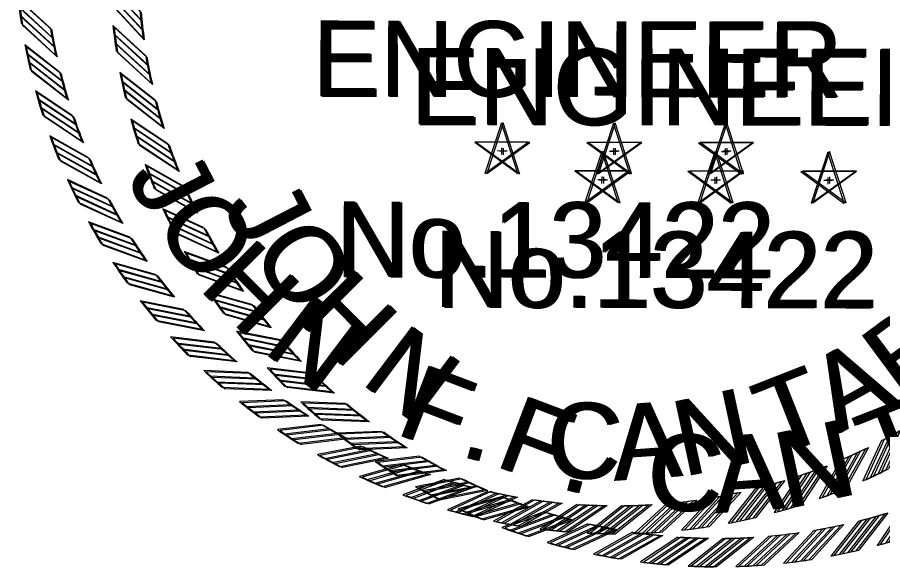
# Model space of a CAD drawing. Extents: x 1373884 to 1377798, y 1168424 to 1170626.
# Drawn here: x 1376716 to 1376888.6, y 1168432.1 to 1168541.9 of the extents above; entities that cross this region are included whole.
import ezdxf

# ---------------------------------------------------------------- set-up
doc = ezdxf.new("R2010")
doc.units = 0
for name, color, linetype in [('Default', 7, 'Continuous'), ('G-ANNO-SYMB', 7, 'Continuous'), ('G-ANNO-TEXT', 7, 'Continuous')]:
    doc.layers.add(name, color=color, linetype=linetype)

# ---------------------------------------------------------------- blocks, each defined once
blk = doc.blocks.new('STAR')
at = {"layer": 'Default'}
for p, q in [((-0.0001, 0.0615), (-0.0366, -0.0504)), ((0.0362, -0.0503), (0, 0.0617)), ((0.0587, 0.0188), (-0.059, 0.0189)), ((-0.0589, 0.0188), (0.0363, -0.0505)), ((-0.0365, -0.0503), (0.0589, 0.0188)), ((-0.0085, 0), (0.009, 0)), ((0, 0.0063), (0, -0.0085))]:
    blk.add_line(p, q, dxfattribs=at)
blk = doc.blocks.new('RP')
at = {"layer": 'Default'}
for p, q in [((-0.0781, 1.2656), (0.003, 1.33)), ((-0.058, 1.2667), (0.0216, 1.3299)), ((-0.0375, 1.2674), (0.0405, 1.3294)), ((-0.0176, 1.2679), (0.059, 1.3287))]:
    blk.add_line(p, q, dxfattribs=at)
for radius, start, end in [(1.33, 87.4562, 89.8699), (1.268, 90.7933, 93.5307)]:
    blk.add_arc((0, 0), radius, start, end, dxfattribs=at)

msp = doc.modelspace()

# ---------------------------------------------------------------- block references
at = {"layer": 'Default'}
for name, p, xscale, yscale, rotation in [('RP', (1376855.59, 1168553.5), 91.1765534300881, 91.17655343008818, 94.30419999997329), ('RP', (1376855.79, 1168553.54), 91.1765534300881, 91.17655343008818, 94.5000001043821), ('RP', (1376855.59, 1168553.5), 91.17655343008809, 91.17655343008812, 98.8041999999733), ('RP', (1376855.79, 1168553.54), 91.17655343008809, 91.17655343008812, 99.0000001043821), ('RP', (1376855.59, 1168553.5), 91.1765534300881, 91.17655343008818, 103.30419999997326), ('RP', (1376855.79, 1168553.54), 91.17655343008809, 91.17655343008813, 103.50000010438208), ('RP', (1376855.59, 1168553.5), 91.1765534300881, 91.1765534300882, 107.80419999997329), ('RP', (1376855.79, 1168553.54), 91.17655343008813, 91.17655343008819, 108.0000001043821), ('RP', (1376855.59, 1168553.5), 91.1765534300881, 91.17655343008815, 112.30419999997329), ('STAR', (1376832.54, 1168509.52), 91.17655343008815, 91.1765534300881, -0.1958000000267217), ('STAR', (1376832.9, 1168509.47), 91.17655343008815, 91.1765534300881, 1.0438208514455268e-07), ('STAR', (1376855.1, 1168509.44), 91.17655343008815, 91.1765534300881, -0.1958000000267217), ('STAR', (1376855.45, 1168509.47), 91.17655343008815, 91.1765534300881, 1.0438208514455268e-07), ('STAR', (1376877.65, 1168509.37), 91.17655343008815, 91.1765534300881, -0.1958000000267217), ('STAR', (1376878.01, 1168509.47), 91.17655343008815, 91.1765534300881, 1.0438208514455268e-07), ('RP', (1376855.79, 1168553.54), 91.1765534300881, 91.17655343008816, 112.5000001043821), ('RP', (1376855.59, 1168553.5), 91.17655343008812, 91.17655343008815, 116.80419999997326), ('RP', (1376855.79, 1168553.54), 91.17655343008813, 91.17655343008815, 117.0000001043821), ('RP', (1376855.59, 1168553.5), 91.17655343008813, 91.17655343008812, 121.30419999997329), ('RP', (1376855.79, 1168553.54), 91.17655343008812, 91.17655343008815, 121.5000001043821), ('RP', (1376855.59, 1168553.5), 91.17655343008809, 91.17655343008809, 125.80419999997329), ('RP', (1376855.79, 1168553.54), 91.17655343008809, 91.17655343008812, 126.00000010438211), ('RP', (1376855.59, 1168553.5), 91.1765534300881, 91.17655343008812, 130.3041999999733), ('RP', (1376855.79, 1168553.54), 91.17655343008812, 91.1765534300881, 130.50000010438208), ('RP', (1376855.59, 1168553.5), 91.17655343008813, 91.17655343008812, 134.8041999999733), ('RP', (1376855.79, 1168553.54), 91.17655343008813, 91.17655343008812, 135.00000010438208), ('RP', (1376855.59, 1168553.5), 91.17655343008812, 91.17655343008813, 139.30419999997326), ('RP', (1376855.79, 1168553.54), 91.17655343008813, 91.17655343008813, 139.50000010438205), ('RP', (1376855.59, 1168553.5), 91.17655343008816, 91.17655343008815, 143.8041999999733), ('RP', (1376855.79, 1168553.54), 91.17655343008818, 91.17655343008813, 144.00000010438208), ('RP', (1376855.59, 1168553.5), 91.17655343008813, 91.17655343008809, 148.3041999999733), ('RP', (1376855.79, 1168553.54), 91.17655343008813, 91.17655343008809, 148.50000010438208), ('RP', (1376855.59, 1168553.5), 91.17655343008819, 91.17655343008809, 152.8041999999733), ('RP', (1376855.79, 1168553.54), 91.17655343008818, 91.17655343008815, 153.00000010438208), ('RP', (1376855.59, 1168553.5), 91.17655343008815, 91.1765534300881, 157.3041999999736), ('RP', (1376855.79, 1168553.54), 91.17655343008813, 91.17655343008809, 157.50000010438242), ('RP', (1376855.59, 1168553.5), 91.17655343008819, 91.17655343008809, 161.8041999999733), ('RP', (1376855.79, 1168553.54), 91.17655343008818, 91.17655343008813, 162.00000010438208), ('RP', (1376855.59, 1168553.5), 91.17655343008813, 91.17655343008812, -162.19580000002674), ('RP', (1376855.79, 1168553.54), 91.17655343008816, 91.1765534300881, -161.99999989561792), ('RP', (1376855.59, 1168553.5), 91.17655343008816, 91.17655343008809, 166.3041999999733), ('RP', (1376855.79, 1168553.54), 91.17655343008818, 91.17655343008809, 166.50000010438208), ('RP', (1376855.59, 1168553.5), 91.17655343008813, 91.17655343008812, -166.69580000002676), ('RP', (1376855.79, 1168553.54), 91.17655343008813, 91.17655343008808, -166.49999989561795), ('RP', (1376855.59, 1168553.5), 91.17655343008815, 91.1765534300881, 170.8041999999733), ('RP', (1376855.79, 1168553.54), 91.17655343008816, 91.17655343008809, 171.00000010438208), ('RP', (1376855.59, 1168553.5), 91.1765534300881, 91.17655343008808, -171.19580000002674), ('RP', (1376855.79, 1168553.54), 91.17655343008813, 91.17655343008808, -170.99999989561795), ('RP', (1376855.59, 1168553.5), 91.17655343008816, 91.1765534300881, 175.3041999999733), ('RP', (1376855.79, 1168553.54), 91.17655343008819, 91.17655343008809, 175.50000010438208), ('RP', (1376855.59, 1168553.5), 91.17655343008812, 91.1765534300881, -175.69580000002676), ('RP', (1376855.79, 1168553.54), 91.17655343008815, 91.17655343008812, -175.49999989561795), ('RP', (1376855.59, 1168553.5), 91.17655343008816, 91.17655343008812, 179.8041999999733), ('RP', (1376855.79, 1168553.54), 91.17655343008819, 91.17655343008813, -179.99999989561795)]:
    msp.add_blockref(name, p, dxfattribs=dict(at, xscale=xscale, yscale=yscale, rotation=rotation))
at = {"layer": 'G-ANNO-SYMB'}
for name, p, xscale, yscale, rotation in [('RP', (1376835.36, 1168558.79), 90.20715837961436, 90.20715837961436, 98.8041999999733), ('RP', (1376835.56, 1168558.82), 90.20715837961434, 90.20715837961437, 99.0000001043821), ('RP', (1376835.36, 1168558.79), 90.20715837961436, 90.2071583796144, 103.30419999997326), ('RP', (1376835.56, 1168558.82), 90.20715837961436, 90.2071583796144, 103.50000010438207), ('RP', (1376835.36, 1168558.79), 90.20715837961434, 90.20715837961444, 107.80419999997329), ('RP', (1376835.56, 1168558.82), 90.20715837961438, 90.20715837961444, 108.0000001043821), ('RP', (1376835.36, 1168558.79), 90.20715837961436, 90.20715837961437, 112.30419999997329), ('RP', (1376835.56, 1168558.82), 90.20715837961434, 90.2071583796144, 112.5000001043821), ('STAR', (1376812.56, 1168515.27), 90.2071583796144, 90.20715837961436, -0.19580000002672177), ('STAR', (1376812.91, 1168515.23), 90.2071583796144, 90.20715837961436, 1.0438208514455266e-07), ('STAR', (1376834.88, 1168515.19), 90.2071583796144, 90.20715837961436, -0.19580000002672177), ('STAR', (1376835.23, 1168515.23), 90.2071583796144, 90.20715837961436, 1.0438208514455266e-07), ('STAR', (1376857.19, 1168515.12), 90.2071583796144, 90.20715837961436, -0.19580000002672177), ('STAR', (1376857.54, 1168515.23), 90.2071583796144, 90.20715837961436, 1.0438208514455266e-07), ('RP', (1376835.36, 1168558.79), 90.20715837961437, 90.2071583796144, 116.80419999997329), ('RP', (1376835.56, 1168558.82), 90.20715837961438, 90.2071583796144, 117.0000001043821), ('RP', (1376835.36, 1168558.79), 90.20715837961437, 90.20715837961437, 121.30419999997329), ('RP', (1376835.56, 1168558.82), 90.20715837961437, 90.20715837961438, 121.5000001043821), ('RP', (1376835.36, 1168558.79), 90.20715837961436, 90.20715837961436, 125.80419999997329), ('RP', (1376835.56, 1168558.82), 90.20715837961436, 90.20715837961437, 126.00000010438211), ('RP', (1376835.36, 1168558.79), 90.20715837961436, 90.20715837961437, 130.3041999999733), ('RP', (1376835.56, 1168558.82), 90.20715837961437, 90.20715837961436, 130.50000010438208), ('RP', (1376835.36, 1168558.79), 90.20715837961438, 90.20715837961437, 134.80419999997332), ('RP', (1376835.56, 1168558.82), 90.2071583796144, 90.20715837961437, 135.00000010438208), ('RP', (1376835.36, 1168558.79), 90.20715837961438, 90.20715837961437, 139.30419999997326), ('RP', (1376835.56, 1168558.82), 90.20715837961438, 90.20715837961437, 139.50000010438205), ('RP', (1376835.36, 1168558.79), 90.20715837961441, 90.20715837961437, 143.8041999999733), ('RP', (1376835.56, 1168558.82), 90.20715837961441, 90.20715837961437, 144.00000010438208), ('RP', (1376835.36, 1168558.79), 90.20715837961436, 90.20715837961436, 148.3041999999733), ('RP', (1376835.56, 1168558.82), 90.20715837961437, 90.20715837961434, 148.50000010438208), ('RP', (1376835.36, 1168558.79), 90.20715837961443, 90.20715837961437, 152.8041999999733), ('RP', (1376835.56, 1168558.82), 90.20715837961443, 90.2071583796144, 153.00000010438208), ('RP', (1376835.36, 1168558.79), 90.20715837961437, 90.20715837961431, -153.1958000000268), ('RP', (1376835.56, 1168558.82), 90.20715837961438, 90.20715837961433, -152.99999989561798), ('RP', (1376835.36, 1168558.79), 90.2071583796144, 90.20715837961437, -157.6958000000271), ('RP', (1376835.56, 1168558.82), 90.20715837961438, 90.20715837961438, -157.4999998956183), ('RP', (1376835.36, 1168558.79), 90.2071583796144, 90.20715837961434, 157.3041999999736), ('RP', (1376835.56, 1168558.82), 90.20715837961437, 90.20715837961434, 157.50000010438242), ('RP', (1376835.56, 1168558.82), 90.20715837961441, 90.20715837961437, -161.99999989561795), ('RP', (1376835.36, 1168558.79), 90.20715837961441, 90.20715837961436, 161.8041999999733), ('RP', (1376835.56, 1168558.82), 90.20715837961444, 90.20715837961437, 162.00000010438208), ('RP', (1376835.36, 1168558.79), 90.2071583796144, 90.20715837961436, -162.19580000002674), ('RP', (1376835.36, 1168558.79), 90.20715837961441, 90.20715837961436, 166.3041999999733), ('RP', (1376835.56, 1168558.82), 90.20715837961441, 90.20715837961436, 166.50000010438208), ('RP', (1376835.36, 1168558.79), 90.2071583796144, 90.20715837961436, -166.69580000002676), ('RP', (1376835.56, 1168558.82), 90.20715837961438, 90.20715837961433, -166.49999989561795), ('RP', (1376835.56, 1168558.82), 90.20715837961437, 90.20715837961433, -170.99999989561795), ('RP', (1376835.36, 1168558.79), 90.2071583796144, 90.20715837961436, 170.8041999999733), ('RP', (1376835.56, 1168558.82), 90.2071583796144, 90.20715837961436, 171.00000010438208), ('RP', (1376835.36, 1168558.79), 90.20715837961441, 90.20715837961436, 175.3041999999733), ('RP', (1376835.56, 1168558.82), 90.20715837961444, 90.20715837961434, 175.50000010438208), ('RP', (1376835.36, 1168558.79), 90.20715837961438, 90.20715837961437, -175.69580000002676), ('RP', (1376835.56, 1168558.82), 90.2071583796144, 90.20715837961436, -175.49999989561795), ('RP', (1376835.36, 1168558.79), 90.20715837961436, 90.20715837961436, -171.19580000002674), ('RP', (1376835.36, 1168558.79), 90.2071583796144, 90.20715837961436, 179.8041999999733), ('RP', (1376835.56, 1168558.82), 90.20715837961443, 90.20715837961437, -179.99999989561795)]:
    msp.add_blockref(name, p, dxfattribs=dict(at, xscale=xscale, yscale=yscale, rotation=rotation))

# ---------------------------------------------------------------- texts
at = {"layer": 'Default'}
for s, height, rotation, p in [('ENGINEER', 15.285, 359.8042, (1376794.33, 1168520.51)), ('ENGINEER', 15.285, 0, (1376794.65, 1168520.33)), ('J', 15.28, 297.2813, (1376756.79, 1168504.38)), ('J', 15.28, 297.4771, (1376757.16, 1168504.07)), ('O', 15.28, 304.1899, (1376762.2, 1168495)), ('O', 15.28, 304.3857, (1376762.61, 1168494.72)), ('No.13422', 15.225, 359.8042, (1376799.03, 1168484.06)), ('No.13422', 15.225, 0, (1376799.48, 1168483.9)), ('H', 15.28, 314.7447, (1376771.22, 1168481.84)), ('H', 15.28, 314.9405, (1376771.67, 1168481.58)), ('N', 15.28, 322.9417, (1376784.12, 1168469.06)), ('N', 15.28, 323.1375, (1376784.62, 1168468.85)), ('F', 15.28, 339.0288, (1376810.8, 1168452.5)), ('F', 15.28, 339.2246, (1376811.35, 1168452.38)), ('T', 15.28, 21.4329, (1376887.56, 1168447.5)), ('T', 15.28, 21.6287, (1376888.13, 1168447.65)), ('N', 15.28, 12.0703, (1376869.12, 1168443.69)), ('N', 15.28, 12.2661, (1376869.7, 1168443.77)), ('C', 15.28, 356.1028, (1376841.13, 1168443.92)), ('C', 15.28, 356.2986, (1376841.71, 1168443.91)), ('A', 15.28, 3.9092, (1376855.15, 1168442.91)), ('A', 15.28, 4.105, (1376855.73, 1168442.94)), ('.', 15.28, 344.7037, (1376823.84, 1168447.98)), ('.', 15.28, 344.8995, (1376824.41, 1168447.91))]:
    msp.add_text(s, height=height, rotation=rotation, dxfattribs=at).set_placement(p)
at = {"layer": 'G-ANNO-TEXT'}
for s, height, rotation, p in [('ENGINEER', 15.122, 359.8042, (1376774.76, 1168526.14)), ('ENGINEER', 15.122, 0, (1376775.07, 1168525.97)), ('J', 15.12, 297.2813, (1376737.61, 1168510.18)), ('J', 15.12, 297.4771, (1376737.98, 1168509.88)), ('O', 15.12, 304.1899, (1376742.97, 1168500.91)), ('O', 15.12, 304.3857, (1376743.37, 1168500.63)), ('No.13422', 15.063, 359.8042, (1376779.41, 1168490.08)), ('No.13422', 15.063, 0, (1376779.85, 1168489.92)), ('H', 15.12, 314.7447, (1376751.89, 1168487.88)), ('H', 15.12, 314.9405, (1376752.33, 1168487.63)), ('N', 15.12, 322.9417, (1376764.66, 1168475.24)), ('N', 15.12, 323.1375, (1376765.14, 1168475.03)), ('B', 15.12, 36.505, (1376892.12, 1168465.24)), ('B', 15.12, 36.7008, (1376892.65, 1168465.47)), ('A', 15.12, 28.8562, (1376879.56, 1168458.65)), ('A', 15.12, 29.052, (1376880.11, 1168458.83)), ('F', 15.12, 339.0288, (1376791.05, 1168458.86)), ('F', 15.12, 339.2246, (1376791.6, 1168458.74)), ('T', 15.12, 21.4329, (1376866.99, 1168453.91)), ('T', 15.12, 21.6287, (1376867.55, 1168454.06)), ('N', 15.12, 12.0703, (1376848.75, 1168450.14)), ('N', 15.12, 12.2661, (1376849.32, 1168450.22)), ('C', 15.12, 356.1028, (1376821.06, 1168450.37)), ('C', 15.12, 356.2986, (1376821.63, 1168450.36)), ('A', 15.12, 3.9092, (1376834.93, 1168449.37)), ('A', 15.12, 4.105, (1376835.5, 1168449.4)), ('.', 15.12, 344.7037, (1376803.95, 1168454.39)), ('.', 15.12, 344.8995, (1376804.51, 1168454.31))]:
    msp.add_text(s, height=height, rotation=rotation, dxfattribs=at).set_placement(p)

doc.saveas('drawing.dxf')
